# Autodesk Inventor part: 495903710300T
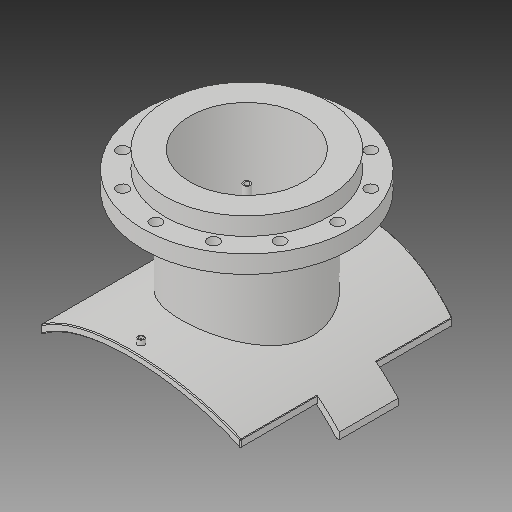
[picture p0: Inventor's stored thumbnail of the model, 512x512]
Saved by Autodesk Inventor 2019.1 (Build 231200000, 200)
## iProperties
Created: 2017-10
Part Number: 495903710300T
Material: Generic
Description: PLASSON FLANGED BRANCH SADDLE 710X300
Document SubType Name: Modeling
Designer: KIM
Mass: 2339.99 g
Surface Area: 3251.55 cm^2
Volume: 2339.99 cm^3
Density: 1 g/cm^3
Appearance: Default
Author: KIM
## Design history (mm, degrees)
derived "495904_495903.ipt"
feature "Solid1::495904_495903.ipt"
feature "Solid2::495904_495903.ipt"
tag "TaggingFeature1"
body "Solid1"
other parameters: "d1" = 15, "d4" = 0, "d6" = 132.5, "d7" = 0, "d12" = 380.6, "d13" = 14, "d14" = 238.5, "d16" = 5 deg, "d18" = 4, "d19" = 14, "d20" = 0, "d21" = 3, "d22" = 0, "d23" = 645, "d36" = 238.5, "d38" = 0, "d39" = 2, "d41" = 257, "d43" = 467, "d46" = 296, "d47" = 16, "d48" = 10.4, "d49" = 192.5, "d51" = 724.2, "d53" = 0, "d54" = 26, "d55" = 205, "d57" = 0, "d59" = 360 deg, "d63" = 0, "d66" = 275, "d67" = 15, "d68" = 137.5, "d70" = 0, "d71" = 2, "H_" = 275, "x_" = 15, "D_" = 16, "DN_" = 257, "D_1" = 467, "s_" = 26
